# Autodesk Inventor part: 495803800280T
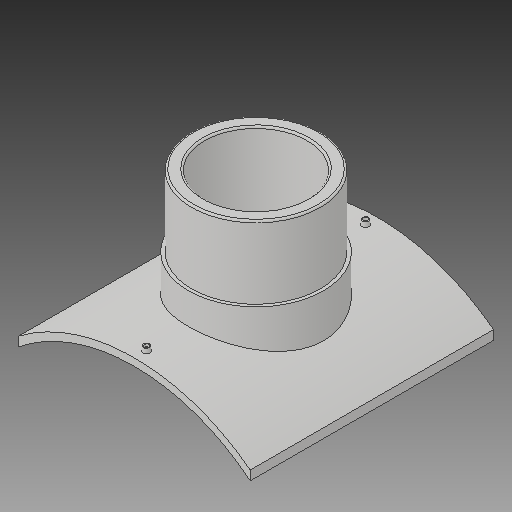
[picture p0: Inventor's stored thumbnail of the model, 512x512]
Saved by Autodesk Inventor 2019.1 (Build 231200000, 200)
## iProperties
Created: 2017-10
Part Number: 495803800280T
Material: Generic
Description: PLASSON BRANCH SADDLE  800x280
Document SubType Name: Modeling
Designer: KIM
Mass: 2754.05 g
Surface Area: 3037.44 cm^2
Volume: 2754.05 cm^3
Density: 1 g/cm^3
Appearance: Default
Author: KIM
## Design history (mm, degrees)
derived "495803.ipt"
feature "Solid1::495803.ipt"
tag "TaggingFeature1"
body "Solid1"
other parameters: "d1" = 16, "d2" = 505, "d4" = 0, "d12" = 425.6, "d13" = 14, "d14" = 238.5, "d16" = 5 deg, "d18" = 4, "d19" = 14, "d20" = 0, "d21" = 3, "d22" = 0, "d23" = 641, "d24" = 294, "d25" = 16, "d26" = 224, "d28" = 0, "d29" = 9.6, "d31" = 0, "d32" = 112.5, "d33" = 0, "d34" = 8, "d37" = 157.5, "d38" = 0, "d39" = 4, "B_" = 505, "H_" = 225, "x_" = 16, "D_" = 16
